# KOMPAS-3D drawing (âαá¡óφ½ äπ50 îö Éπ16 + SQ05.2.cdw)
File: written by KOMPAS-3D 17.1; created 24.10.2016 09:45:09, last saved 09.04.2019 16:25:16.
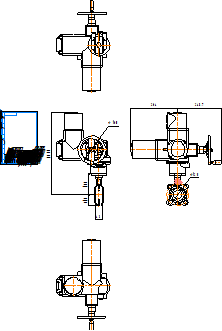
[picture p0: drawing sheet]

Sheet 1: A4, portrait

Title block, sheet 1: name: Гранвэл Ду50 МФ Ру16 + / SQ05.2; material: Внимание! Данный продукт является объектом авторского права ООО «Торговый Дом АДЛ». / Запрещается изменение, копирование, распространение / (в том числе путем копирования на другие сайты и ресурсы в Интернете) / или любое иное использование информации и объектов без предварительного / согласия правообладателя (ООО «Торговый Дом АДЛ»).; mass: 25,6; sheets: 1; organisation: ООО "Торговый дом АДЛ"; sheet format: A4; stored path: \\adlc.lan\data\АДЛ_ПКД\3D-модели\ADL production\Дисковые поворотные затворы ГРАНВЭЛ\межфланцевый с эл.приводом Auma Ру 16\KOMPAS 2D\Гранвэл Ду50 МФ Ру16 + SQ05.2.cdw

Views: Вид 1, Проекционный вид 2, Проекционный вид 3, Проекционный вид 4
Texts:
  Klimkovich
  ADL
Dimensions and other numbers on the sheet: 43; 463,5; 160; 61,5; 120; 125; 248,7; 264; 1:1; 1; 25,6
